(* Logix 5000 project; controller Test vendor 1 type 14 code 92 rev 33.11; software revision 33.03 *)

TASK MainTask (continuous, watchdog 500 ms) : MainProgram

MODULES
   Local : vendor 1 type 14 code 92 (ICP 0, rev 33.11)
      IN : vendor 1 type 7 code 1 (ICP 3, rev 3.2, Input RPI 20 ms)
      O : vendor 1 type 7 code 15 (ICP 2, rev 3.2, Output RPI 20 ms)
      Ethernet : 1756-ENBT (ICP 1, Ethernet 192.168.0.98, rev 6.4)
         IOLM1 : DXM (Ethernet 192.168.0.1, rev 2.22, StandardDataDriven RPI 20 ms)
END_MODULES

TYPE Banner_B25_Configuration_v4 :
STRUCT
   Sensor_Lockout : SINT;   // 0=Unlocked, 1=Locked
   Sensitivity : SINT;   // 0=Low, 1=Standard, 2=High
   Pin2_Function : SINT;   // 0=Disabled, 1=Remote Teach, 2=Detection Output, 3=Complementary Output, 4=NC Health, 5=NO Health
   Pin2_Pin4_Polarity : SINT;   // 0=NPN, 1=PNP, 2=Push Pull
   Output_Logic : SINT;   // 0=LO, 1= DO
   Output_Delay_Mode : SINT;   // 0=No Delay, 1=On/Off Delay
   Output_On_Delay : DINT;
   Output_Off_Delay : DINT;
   Dynamic_Teach_Timeout_Mode : SINT;   // 0=Cancel Teach, 1=Stop Teach
   Dynamic_Teach_Timeout_Duration : DINT;
   Alarm_Threshold : SINT;   // Set to 0% to disable alarm. Thresholds close to 100% will alarm near taught condition, thrsholds near 0% will alarm near sensor limits
   Display_Disable : SINT;   // 0=Enabled, 1=Disabled
   Drift_Filter_Enable : SINT;   // 0=Disabled, 1=Enabled
   Signal_Mode : SINT;   // Signal Mode - Signal places 100% at taught condition and 0% at no signal. Switchpoint Centric paces 100% at taught conditition and 50% at switchpoint.
END_STRUCT
END_TYPE

TYPE Banner_B25_PDI_v4 :   // Process Data for a B25. This will include event information.
STRUCT
   Output_State : SINT;   // 0 = Inactive, 1 = Active
   Alarm_State : SINT;   // 0 = Inactive, 1 = Active
   Signal_Level : SINT;   // Signal Mode - Signal places 100% at taught condition and 0% at no signal. Switchpoint Centric paces 100% at taught conditition and 50% at switchpoint.
END_STRUCT
END_TYPE

TYPE Banner_B25_RD_v4 :   // UDT that stores the Read Data for a B25.
STRUCT
   Direct : Banner_Direct_Parameters_v4;
   Serial_Number : STRING;
   Teach_State : SINT;   // 0=Idle, 1=SP1 Success, 2=SP2 Succes, 3=SP1 SP2 Success, 4 = Wait for Command, 5 = Busy, 7 = Error.
   Status : Banner_B25_Status_v4;
   All_Time_Run_Time_Counter : DINT;   // 0 to 2 Billion. 1/4 hr increments.
END_STRUCT
END_TYPE

TYPE Banner_B25_Status_v4 :
STRUCT
   Output_State : SINT;   // 0=Inactive, 1=Active
   Signal_Level : SINT;   // Signal Level - Switchpoit is at 50%, Taught Signal is at 100%
   Temperature : DINT;   // Internal Temperature
   Last_Taught_Temperature : DINT;   // Internal Temperature the last time device was taught
   Quality_of_Teach : SINT;   // 0=Not Taught, 1=Good, 2=Bad
   Health_Alarm_State : SINT;   // 0=No Alarm, 1= Alarm
   Quality_of_Health : INT;
END_STRUCT
END_TYPE

TYPE Banner_B25_v4 :   // All of the parameters for a B25.
STRUCT
   Initial_Global_Read : BOOL;   // Determines if all of the IO-Link data has been read into the PLC yet
   Command : INT;   // Value placed in here will activate a read or write to a specifc IO-Link Index
   Read : Banner_B25_RD_v4;   // Read Only Data
   Write : Banner_B25_WD_v4;   // Write Data
   Reset : BOOL;   // Resets AOI. This will force a complete parameter read of the sensor.
END_STRUCT
END_TYPE

TYPE Banner_B25_WD_v4 :   // UDT that stores the Write Data for a B25.
STRUCT
   System_Command : INT;   // See IODD file for list of commands that can be activated via the System Command interface
   Parameter_Access_Lock : SINT;   // Write access to all parameters is prohibited while value is 1. Only this parameter can be adjusted when value is 1.
   Data_Storage_Lock : SINT;   // Automatic data storage is disabled when this value is equal to 1. Read access is not affected.
   Local_Parameterization_Lock : SINT;   // Parameterization via local control elements on device is disabled.
   Local_User_Interface_Lock : SINT;   // Operation of local user interface is disabled.
   Configuration : Banner_B25_Configuration_v4;
   Resettable_Run_Time_Counter : DINT;   // 0 to 2 Billion. 1/4 hr increments.
   All_Time_Run_Time_Event_Time : DINT;   // 0 to 2 Billion. 1/4 hr increments.
   Resettable_Run_Time_Event_Time_Counter : DINT;   // 0 to 2 Billion. 1/4 hr increments.
END_STRUCT
END_TYPE

TYPE Banner_Direct_Parameters_v4 :
STRUCT
   Master_Cycle_Time : INT;
   Min_Cycle_Time : INT;
   M_Sequence_Capability : INT;
   IO_Link_Version_ID : INT;
   Process_Data_Input_Length : INT;
   Process_Data_Output_Length : INT;
   Combined_Vendor_ID : DINT;   // IO-Link Vendor ID
   Vendor_ID1 : INT;
   Vendor_ID2 : INT;
   Combined_Device_ID : DINT;   // IO-Link Device ID
   Device_ID1 : INT;
   Device_ID2 : INT;
   Device_ID3 : INT;
END_STRUCT
END_TYPE

TYPE Banner_IOL_Port_v4 :   // UDT that has all of the data items necessary to communicate with a specific Port on a IO-Link Master
STRUCT
   Port_Controlled : INT;   // Each bit represents a port on an IO-Link Master. Set to 1 to tell AOI to control that port.
   Port_Activate : INT;   // Each bit represents a port on an IO-Link Master. When ON that port will process any commands in queue.
   Port_Read : INT;   // Each bit represents a port on an IO-Link Master. Used to determine when device AOI has requested a Read command.
   Port_Write : INT;   // Each bit represents a port on an IO-Link Master. Used to determine when device AOI has requested a Write command.
   Port_RW_Complete : INT;   // Each bit represents a port on an IO-Link Master. Tells device AOI that Read or Write request has been completed.
   Port_Device_Read : INT;
   Data_Transfer : SINT[190];   // Array to transfer data from IO-Master to device AOIs.
END_STRUCT
END_TYPE

TYPE Banner_IOLM_EL_v4 :   // Error Log for Messages to IOLM.
STRUCT
   RW : SINT;   // 0 = Read, 1 = Write.
   Port : SINT;   // Port number that generated error.
   Index : INT;   // IO-Link Index for generated error.
END_STRUCT
END_TYPE

TYPE Banner_IOLM_v4 :   // UDT to control IO-Link Masters.
STRUCT
   Message_Source_Data : SINT[190];
   Message_Destination_Data : SINT[190];
   Error_Log : Banner_IOLM_EL_v4[10];
   Error_Write_Retry : BOOL;
   Num_Error_MSGS : DINT;
   IO_Link_Master_Busy : BOOL;   // 0 = While waiting for a command, 1 = Processing command
   AOI_Reset : BOOL;
   Port_Data : Banner_IOL_Port_v4;   // All of the necessary data to work with the various ports of the IO-Link Master.
   Halt_Operation : BOOL;   // When parameter is 1 the AOI is halted as next available time frame.
   AOI_Halted : BOOL;   // AOI is in standby mode until Halt Operation tag is set back to 0.
END_STRUCT
END_TYPE

ADD_ON_INSTRUCTION Banner_B25_Param_v4   (* revision 4.0, vendor Banner Engineering *)
// AOI to read and write parameter data to an IO-Link B25.
VAR_IN_OUT
   B25 : Banner_B25_v4; {required}
   Port_Data : Banner_IOL_Port_v4; {required}
END_VAR
VAR_INPUT
   Port : DINT; {required}
END_VAR
VAR
   Local_Control : DINT; {access None}
   Global_Read_Command_Value : INT; {access None}
   Global_Write_Command_Value : INT; {access None}
   Command_Being_Processed : BOOL; {access None}
   Update_Archive : BOOL; {access None}
   Index_Write_Inprocess : INT; {access None}
   Index_Write_Control : INT; {access None}
   Inprocess_Index : DINT; {access None}
END_VAR

ROUTINE Logic   (* ladder *)
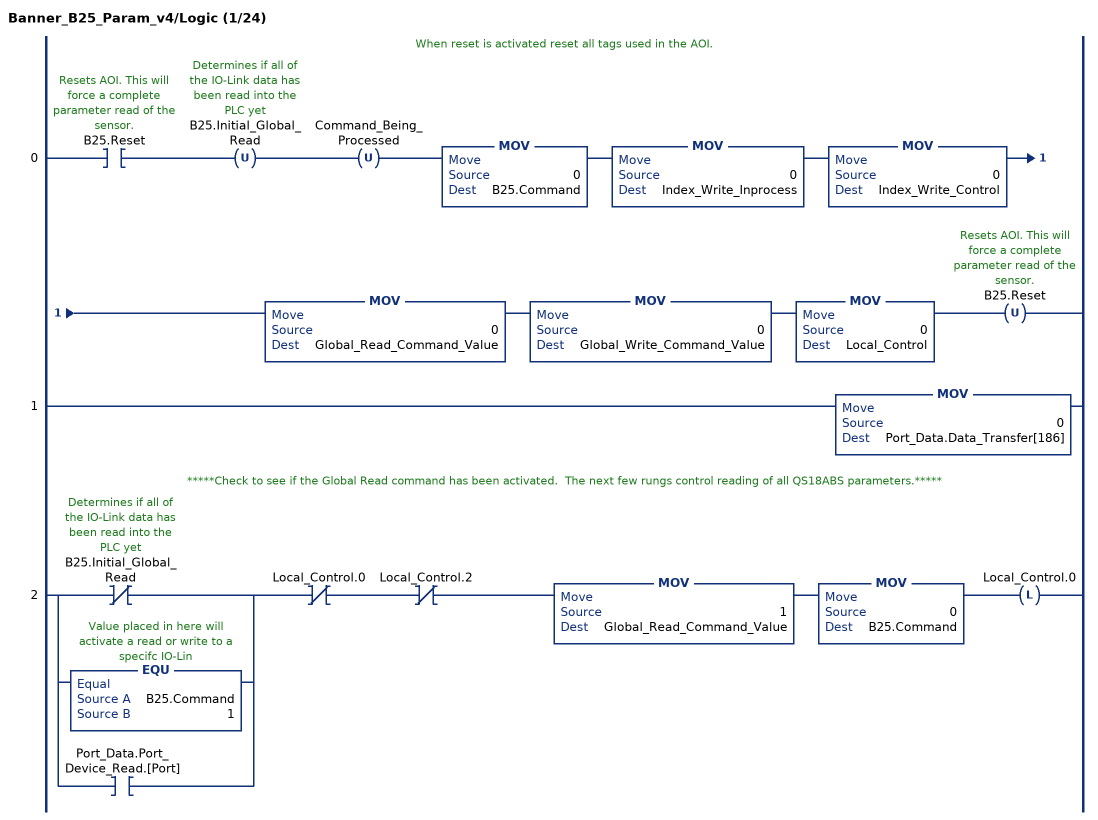
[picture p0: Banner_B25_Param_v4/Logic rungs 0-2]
   // When reset is activated reset all tags used in the AOI.
   0: XIC(B25.Reset)OTU(B25.Initial_Global_Read)OTU(Command_Being_Processed)MOV(0,B25.Command)MOV(0,Index_Write_Inprocess)MOV(0,Index_Write_Control)MOV(0,Global_Read_Command_Value)MOV(0,Global_Write_Command_Value)MOV(0,Local_Control)OTU(B25.Reset);
   1: MOV(0,Port_Data.Data_Transfer[186]);
   // *****Check to see if the Global Read command has been activated.  The next few rungs control reading of all QS18ABS parameters.*****
   2: [XIO(B25.Initial_Global_Read) ,EQU(B25.Command,1) ,XIC(Port_Data.Port_Device_Read.[Port]) ]XIO(Local_Control.0)XIO(Local_Control.2)MOV(1,Global_Read_Command_Value)MOV(0,B25.Command)OTL(Local_Control.0);
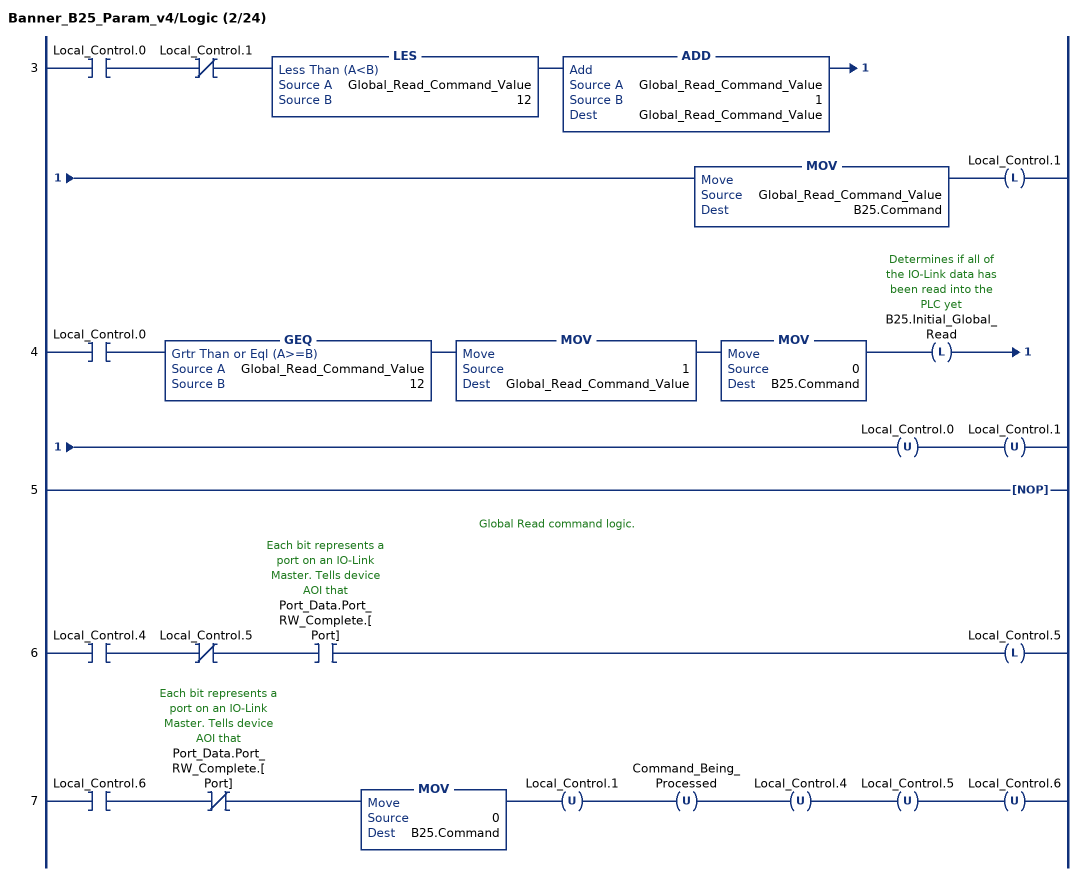
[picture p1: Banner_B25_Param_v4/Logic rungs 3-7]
   3: XIC(Local_Control.0)XIO(Local_Control.1)LES(Global_Read_Command_Value,12)ADD(Global_Read_Command_Value,1,Global_Read_Command_Value)MOV(Global_Read_Command_Value,B25.Command)OTL(Local_Control.1);
   4: XIC(Local_Control.0)GEQ(Global_Read_Command_Value,12)MOV(1,Global_Read_Command_Value)MOV(0,B25.Command)OTL(B25.Initial_Global_Read)OTU(Local_Control.0)OTU(Local_Control.1);
   5: NOP();
   // Global Read command logic.
   6: XIC(Local_Control.4)XIO(Local_Control.5)XIC(Port_Data.Port_RW_Complete.[Port])OTL(Local_Control.5);
   7: XIC(Local_Control.6)XIO(Port_Data.Port_RW_Complete.[Port])MOV(0,B25.Command)OTU(Local_Control.1)OTU(Command_Being_Processed)OTU(Local_Control.4)OTU(Local_Control.5)OTU(Local_Control.6);
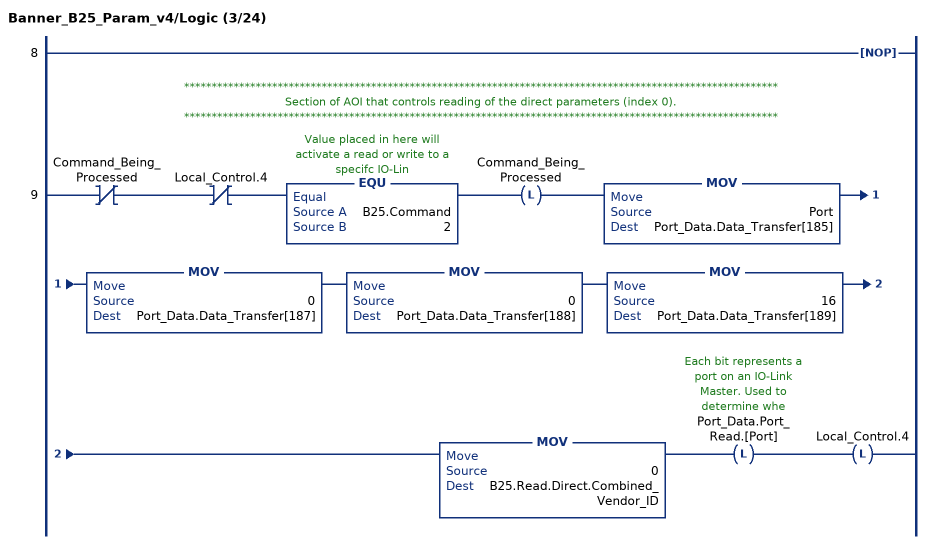
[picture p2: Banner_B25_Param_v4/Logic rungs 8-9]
   8: NOP();
   // ************************************************************************************************************
   // Section of AOI that controls reading of the direct parameters (index 0).
   // ************************************************************************************************************
   9: XIO(Command_Being_Processed)XIO(Local_Control.4)EQU(B25.Command,2)OTL(Command_Being_Processed)MOV(Port,Port_Data.Data_Transfer[185])MOV(0,Port_Data.Data_Transfer[187])MOV(0,Port_Data.Data_Transfer[188])MOV(16,Port_Data.Data_Transfer[189])MOV(0,B25.Read.Direct.Combined_Vendor_ID)OTL(Port_Data.Port_Read.[Port])OTL(Local_Control.4);
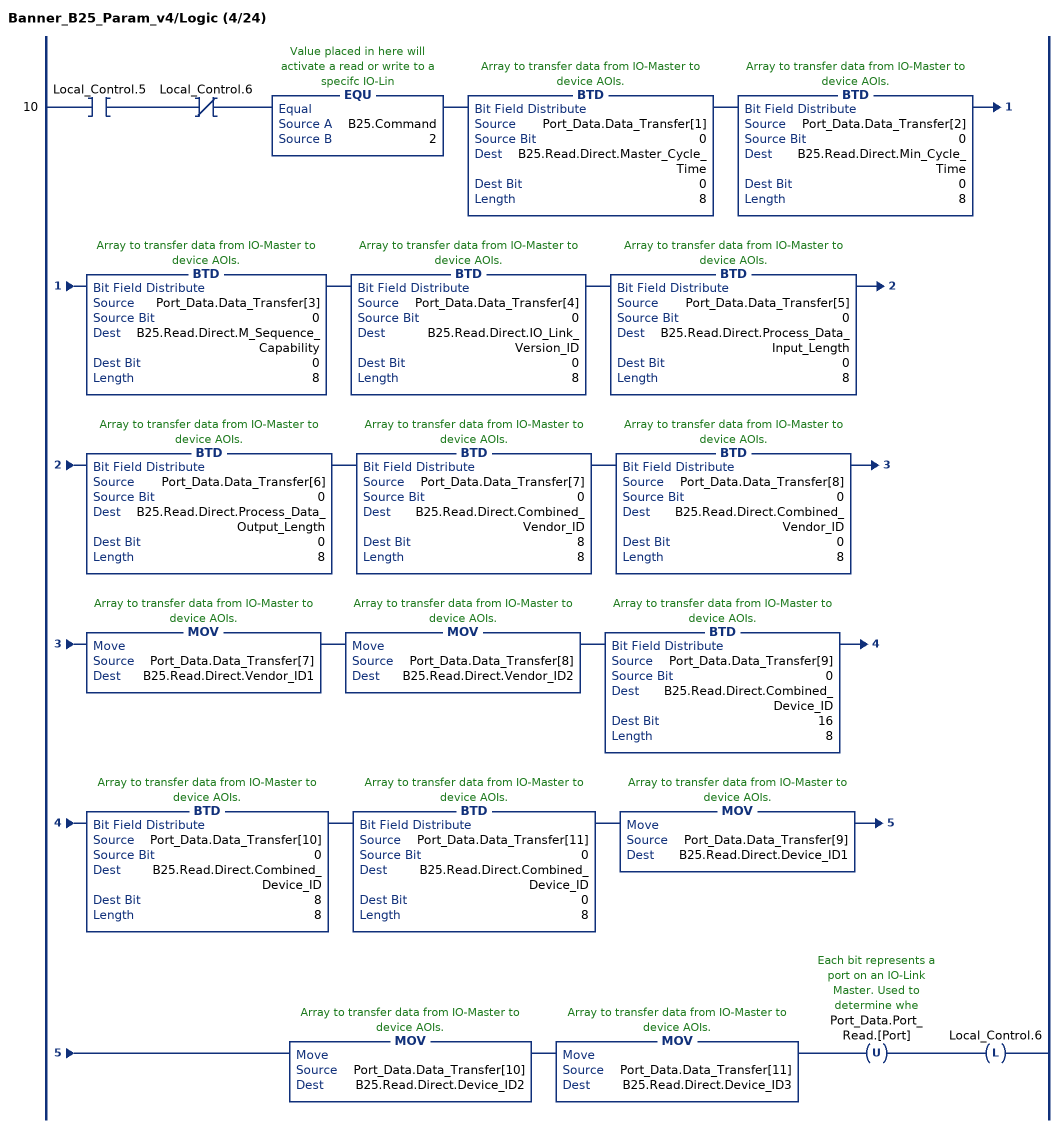
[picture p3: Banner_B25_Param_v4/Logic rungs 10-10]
   10: XIC(Local_Control.5)XIO(Local_Control.6)EQU(B25.Command,2)BTD(Port_Data.Data_Transfer[1],0,B25.Read.Direct.Master_Cycle_Time,0,8)BTD(Port_Data.Data_Transfer[2],0,B25.Read.Direct.Min_Cycle_Time,0,8)BTD(Port_Data.Data_Transfer[3],0,B25.Read.Direct.M_Sequence_Capability,0,8)BTD(Port_Data.Data_Transfer[4],0,B25.Read.Direct.IO_Link_Version_ID,0,8)BTD(Port_Data.Data_Transfer[5],0,B25.Read.Direct.Process_Data_Input_Length,0,8)BTD(Port_Data.Data_Transfer[6],0,B25.Read.Direct.Process_Data_Output_Length,0,8)BTD(Port_Data.Data_Transfer[7],0,B25.Read.Direct.Combined_Vendor_ID,8,8)BTD(Port_Data.Data_Transfer[8],0,B25.Read.Direct.Combined_Vendor_ID,0,8)MOV(Port_Data.Data_Transfer[7],B25.Read.Direct.Vendor_ID1)MOV(Port_Data.Data_Transfer[8],B25.Read.Direct.Vendor_ID2)BTD(Port_Data.Data_Transfer[9],0,B25.Read.Direct.Combined_Device_ID,16,8)BTD(Port_Data.Data_Transfer[10],0,B25.Read.Direct.Combined_Device_ID,8,8)BTD(Port_Data.Data_Transfer[11],0,B25.Read.Direct.Combined_Device_ID,0,8)MOV(Port_Data.Data_Transfer[9],B25.Read.Direct.Device_ID1)MOV(Port_Data.Data_Transfer[10],B25.Read.Direct.Device_ID2)MOV(Port_Data.Data_Transfer[11],B25.Read.Direct.Device_ID3)OTU(Port_Data.Port_Read.[Port])OTL(Local_Control.6);
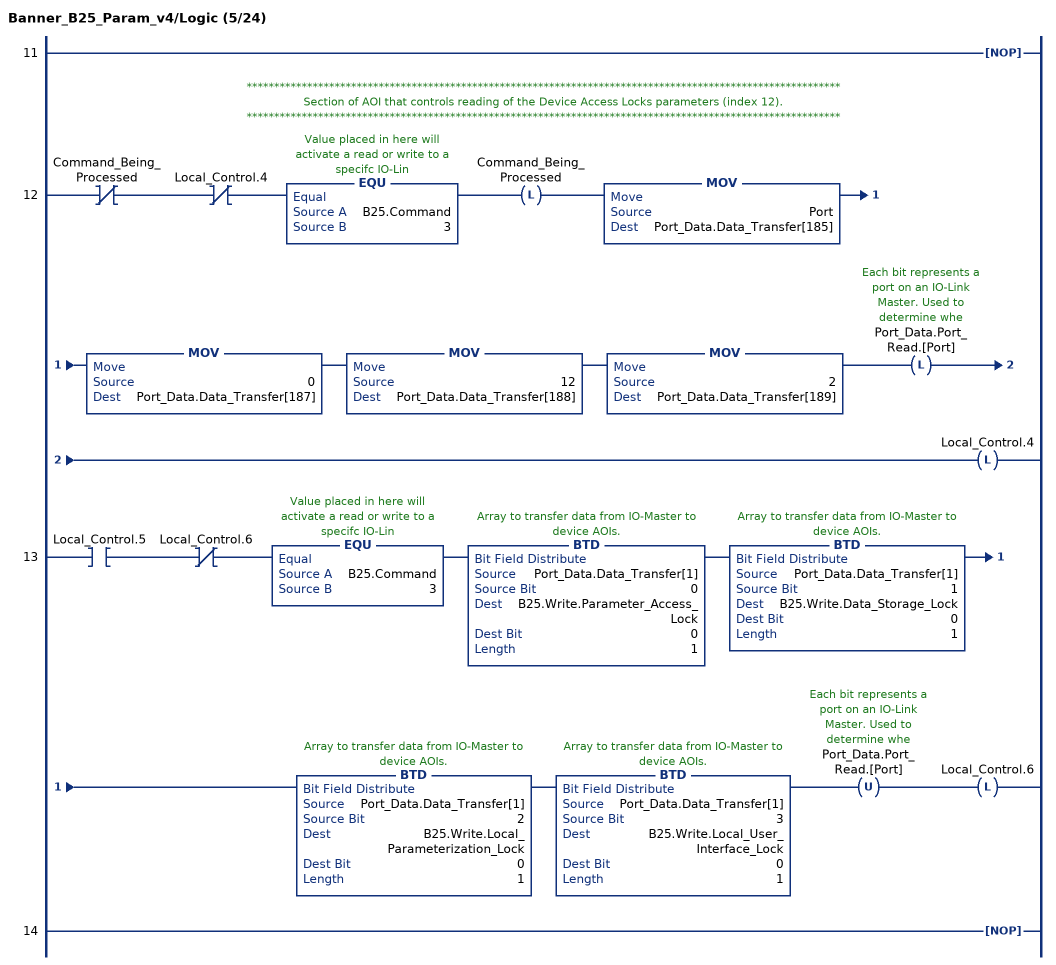
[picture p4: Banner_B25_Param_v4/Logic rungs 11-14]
   11: NOP();
   // ************************************************************************************************************
   // Section of AOI that controls reading of the Device Access Locks parameters (index 12).
   // ************************************************************************************************************
   12: XIO(Command_Being_Processed)XIO(Local_Control.4)EQU(B25.Command,3)OTL(Command_Being_Processed)MOV(Port,Port_Data.Data_Transfer[185])MOV(0,Port_Data.Data_Transfer[187])MOV(12,Port_Data.Data_Transfer[188])MOV(2,Port_Data.Data_Transfer[189])OTL(Port_Data.Port_Read.[Port])OTL(Local_Control.4);
   13: XIC(Local_Control.5)XIO(Local_Control.6)EQU(B25.Command,3)BTD(Port_Data.Data_Transfer[1],0,B25.Write.Parameter_Access_Lock,0,1)BTD(Port_Data.Data_Transfer[1],1,B25.Write.Data_Storage_Lock,0,1)BTD(Port_Data.Data_Transfer[1],2,B25.Write.Local_Parameterization_Lock,0,1)BTD(Port_Data.Data_Transfer[1],3,B25.Write.Local_User_Interface_Lock,0,1)OTU(Port_Data.Port_Read.[Port])OTL(Local_Control.6);
   14: NOP();
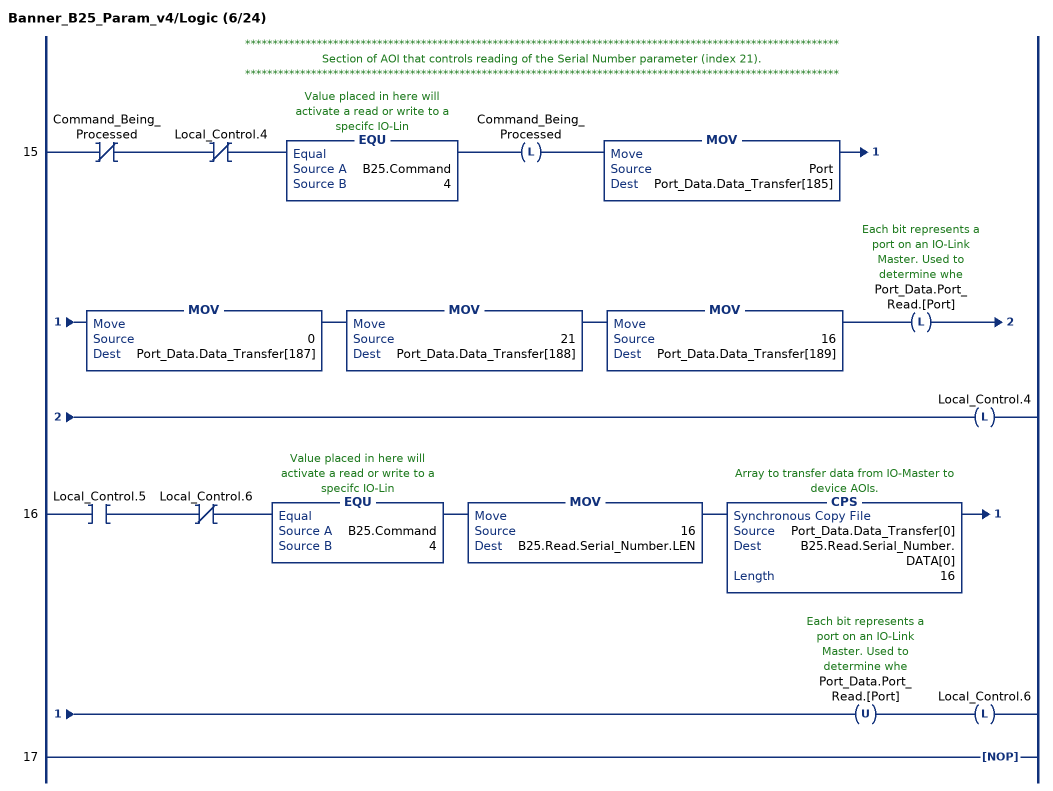
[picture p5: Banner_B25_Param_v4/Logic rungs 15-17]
   // ************************************************************************************************************
   // Section of AOI that controls reading of the Serial Number parameter (index 21).
   // ************************************************************************************************************
   15: XIO(Command_Being_Processed)XIO(Local_Control.4)EQU(B25.Command,4)OTL(Command_Being_Processed)MOV(Port,Port_Data.Data_Transfer[185])MOV(0,Port_Data.Data_Transfer[187])MOV(21,Port_Data.Data_Transfer[188])MOV(16,Port_Data.Data_Transfer[189])OTL(Port_Data.Port_Read.[Port])OTL(Local_Control.4);
   16: XIC(Local_Control.5)XIO(Local_Control.6)EQU(B25.Command,4)MOV(16,B25.Read.Serial_Number.LEN)CPS(Port_Data.Data_Transfer[0],B25.Read.Serial_Number.DATA[0],16)OTU(Port_Data.Port_Read.[Port])OTL(Local_Control.6);
   17: NOP();
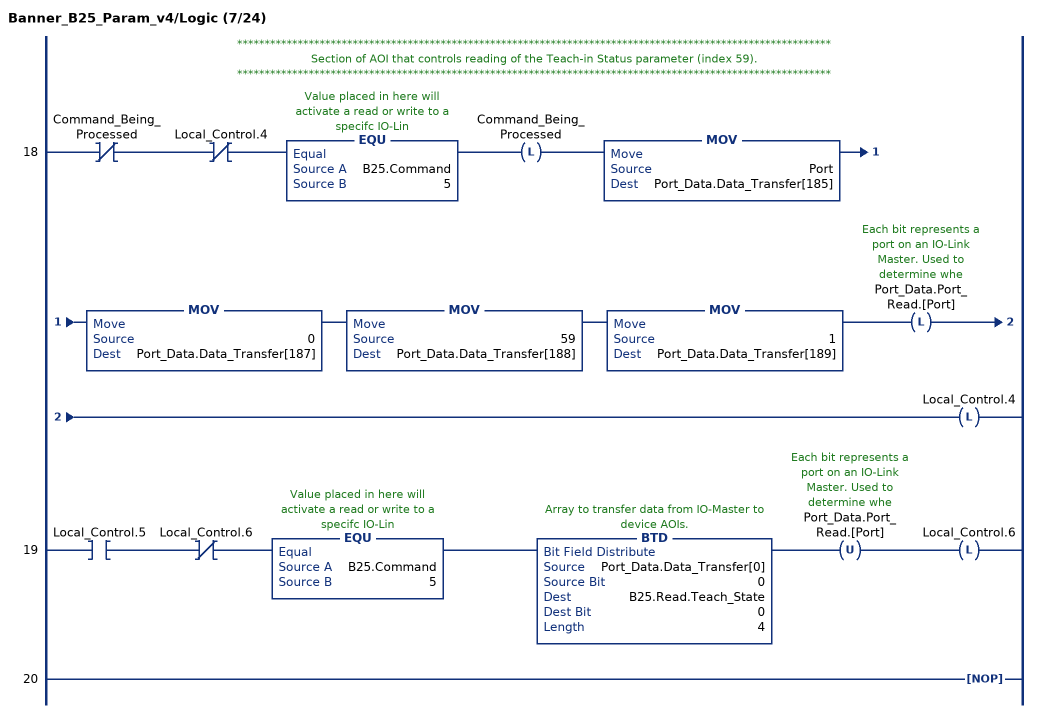
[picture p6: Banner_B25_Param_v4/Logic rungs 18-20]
   // ************************************************************************************************************
   // Section of AOI that controls reading of the Teach-in Status parameter (index 59).
   // ************************************************************************************************************
   18: XIO(Command_Being_Processed)XIO(Local_Control.4)EQU(B25.Command,5)OTL(Command_Being_Processed)MOV(Port,Port_Data.Data_Transfer[185])MOV(0,Port_Data.Data_Transfer[187])MOV(59,Port_Data.Data_Transfer[188])MOV(1,Port_Data.Data_Transfer[189])OTL(Port_Data.Port_Read.[Port])OTL(Local_Control.4);
   19: XIC(Local_Control.5)XIO(Local_Control.6)EQU(B25.Command,5)BTD(Port_Data.Data_Transfer[0],0,B25.Read.Teach_State,0,4)OTU(Port_Data.Port_Read.[Port])OTL(Local_Control.6);
   20: NOP();
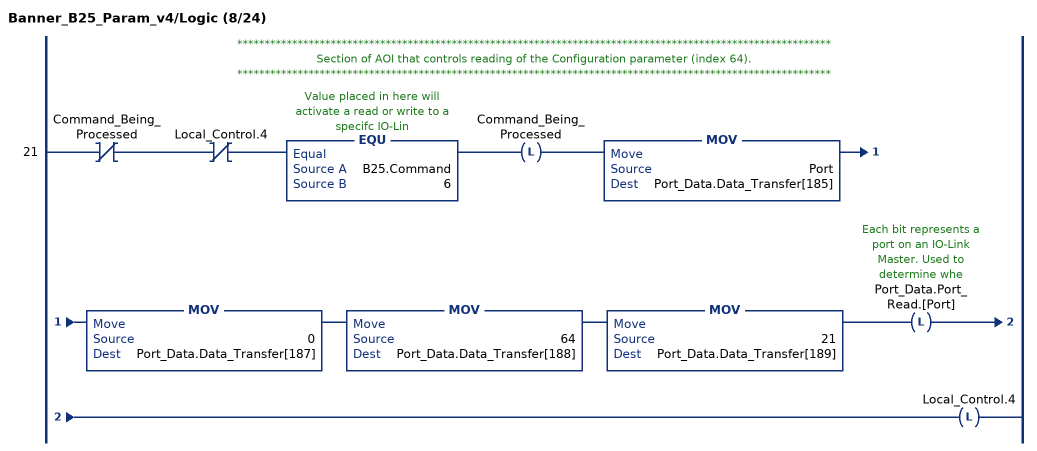
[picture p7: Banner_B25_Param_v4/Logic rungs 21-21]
   // ************************************************************************************************************
   // Section of AOI that controls reading of the Configuration parameter (index 64).
   // ************************************************************************************************************
   21: XIO(Command_Being_Processed)XIO(Local_Control.4)EQU(B25.Command,6)OTL(Command_Being_Processed)MOV(Port,Port_Data.Data_Transfer[185])MOV(0,Port_Data.Data_Transfer[187])MOV(64,Port_Data.Data_Transfer[188])MOV(21,Port_Data.Data_Transfer[189])OTL(Port_Data.Port_Read.[Port])OTL(Local_Control.4);
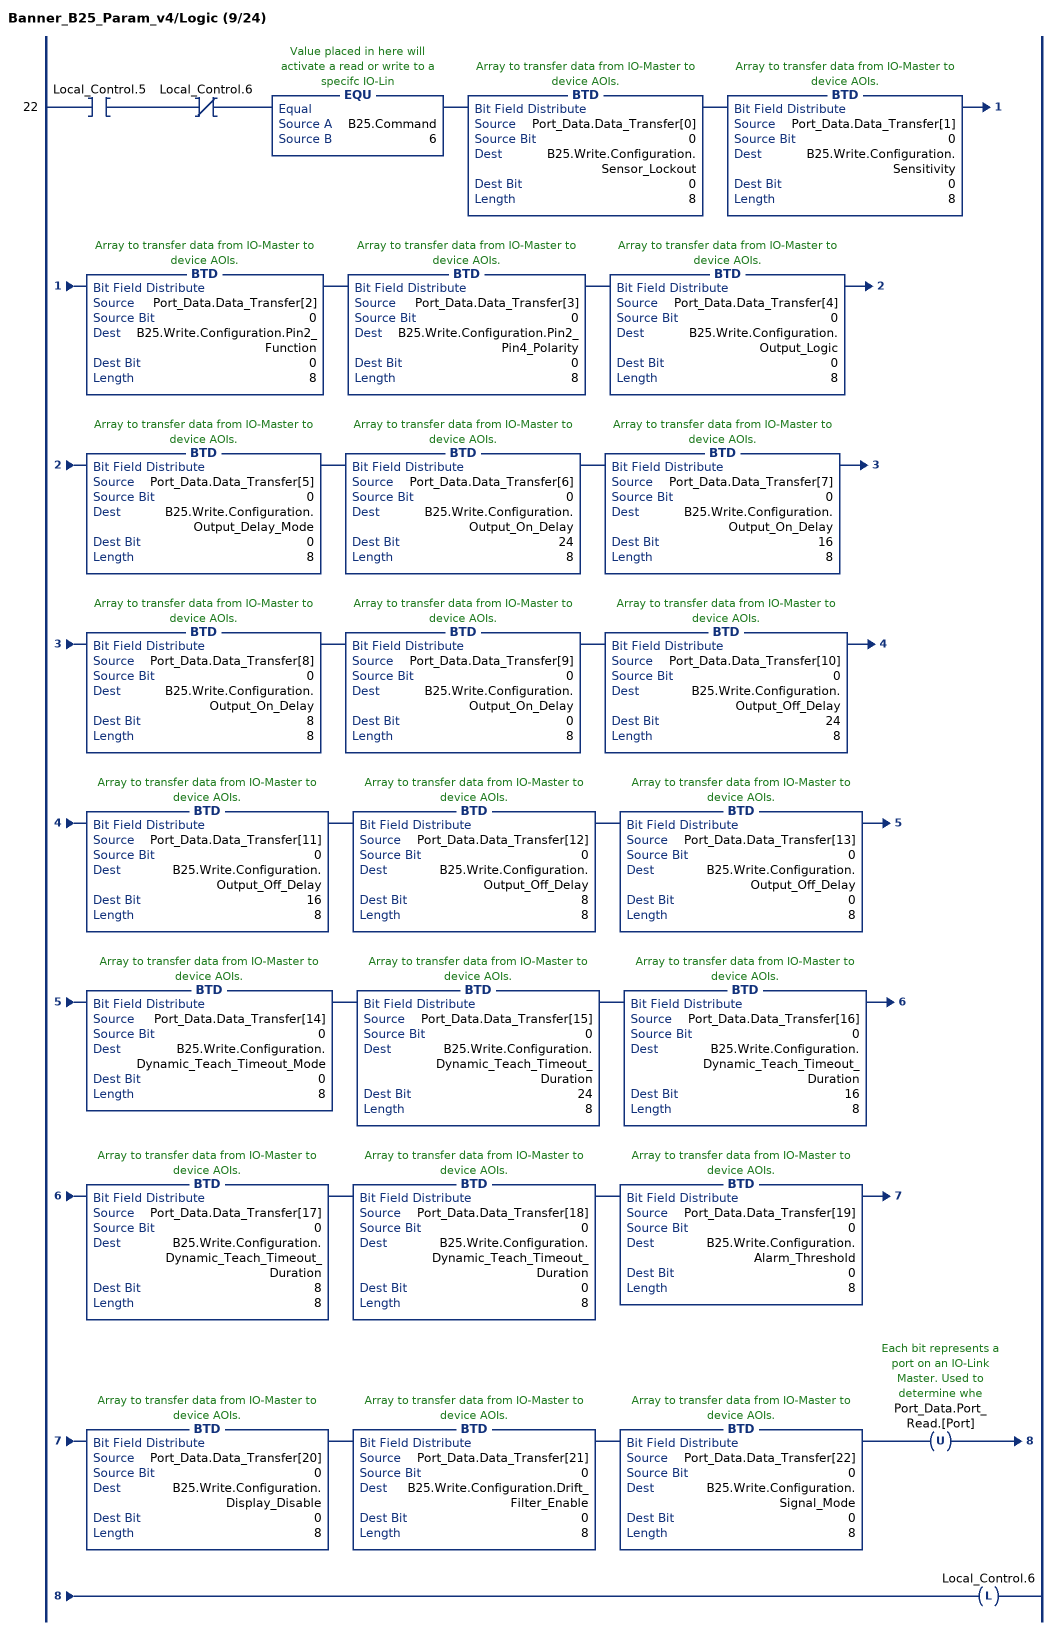
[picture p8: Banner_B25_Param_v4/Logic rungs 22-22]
   22: XIC(Local_Control.5)XIO(Local_Control.6)EQU(B25.Command,6)BTD(Port_Data.Data_Transfer[0],0,B25.Write.Configuration.Sensor_Lockout,0,8)BTD(Port_Data.Data_Transfer[1],0,B25.Write.Configuration.Sensitivity,0,8)BTD(Port_Data.Data_Transfer[2],0,B25.Write.Configuration.Pin2_Function,0,8)BTD(Port_Data.Data_Transfer[3],0,B25.Write.Configuration.Pin2_Pin4_Polarity,0,8)BTD(Port_Data.Data_Transfer[4],0,B25.Write.Configuration.Output_Logic,0,8)BTD(Port_Data.Data_Transfer[5],0,B25.Write.Configuration.Output_Delay_Mode,0,8)BTD(Port_Data.Data_Transfer[6],0,B25.Write.Configuration.Output_On_Delay,24,8)BTD(Port_Data.Data_Transfer[7],0,B25.Write.Configuration.Output_On_Delay,16,8)BTD(Port_Data.Data_Transfer[8],0,B25.Write.Configuration.Output_On_Delay,8,8)BTD(Port_Data.Data_Transfer[9],0,B25.Write.Configuration.Output_On_Delay,0,8)BTD(Port_Data.Data_Transfer[10],0,B25.Write.Configuration.Output_Off_Delay,24,8)BTD(Port_Data.Data_Transfer[11],0,B25.Write.Configuration.Output_Off_Delay,16,8)BTD(Port_Data.Data_Transfer[12],0,B25.Write.Configuration.Output_Off_Delay,8,8)BTD(Port_Data.Data_Transfer[13],0,B25.Write.Configuration.Output_Off_Delay,0,8)BTD(Port_Data.Data_Transfer[14],0,B25.Write.Configuration.Dynamic_Teach_Timeout_Mode,0,8)BTD(Port_Data.Data_Transfer[15],0,B25.Write.Configuration.Dynamic_Teach_Timeout_Duration,24,8)BTD(Port_Data.Data_Transfer[16],0,B25.Write.Configuration.Dynamic_Teach_Timeout_Duration,16,8)BTD(Port_Data.Data_Transfer[17],0,B25.Write.Configuration.Dynamic_Teach_Timeout_Duration,8,8)BTD(Port_Data.Data_Transfer[18],0,B25.Write.Configuration.Dynamic_Teach_Timeout_Duration,0,8)BTD(Port_Data.Data_Transfer[19],0,B25.Write.Configuration.Alarm_Threshold,0,8)BTD(Port_Data.Data_Transfer[20],0,B25.Write.Configuration.Display_Disable,0,8)BTD(Port_Data.Data_Transfer[21],0,B25.Write.Configuration.Drift_Filter_Enable,0,8)BTD(Port_Data.Data_Transfer[22],0,B25.Write.Configuration.Signal_Mode,0,8)OTU(Port_Data.Port_Read.[Port])OTL(Local_Control.6);
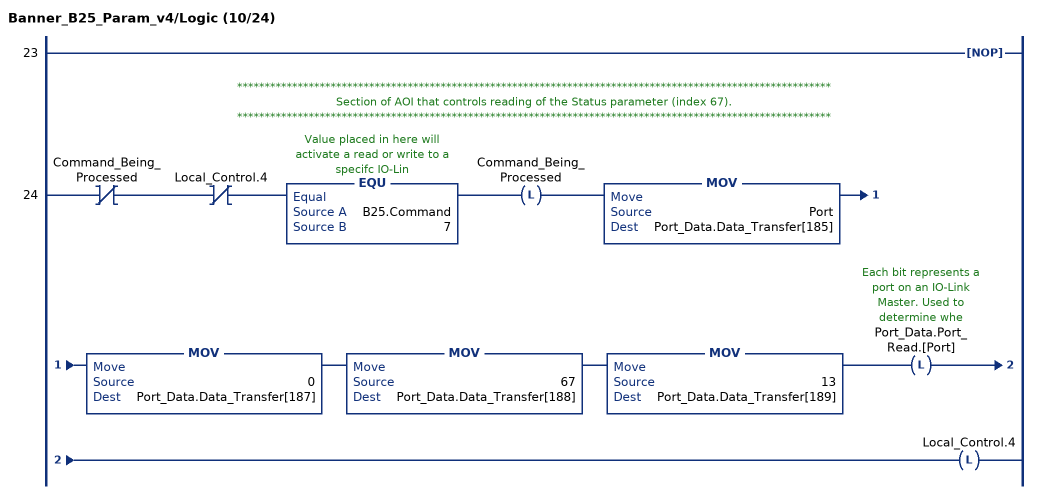
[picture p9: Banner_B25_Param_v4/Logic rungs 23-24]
   23: NOP();
   // ************************************************************************************************************
   // Section of AOI that controls reading of the Status parameter (index 67).
   // ************************************************************************************************************
   24: XIO(Command_Being_Processed)XIO(Local_Control.4)EQU(B25.Command,7)OTL(Command_Being_Processed)MOV(Port,Port_Data.Data_Transfer[185])MOV(0,Port_Data.Data_Transfer[187])MOV(67,Port_Data.Data_Transfer[188])MOV(13,Port_Data.Data_Transfer[189])OTL(Port_Data.Port_Read.[Port])OTL(Local_Control.4);
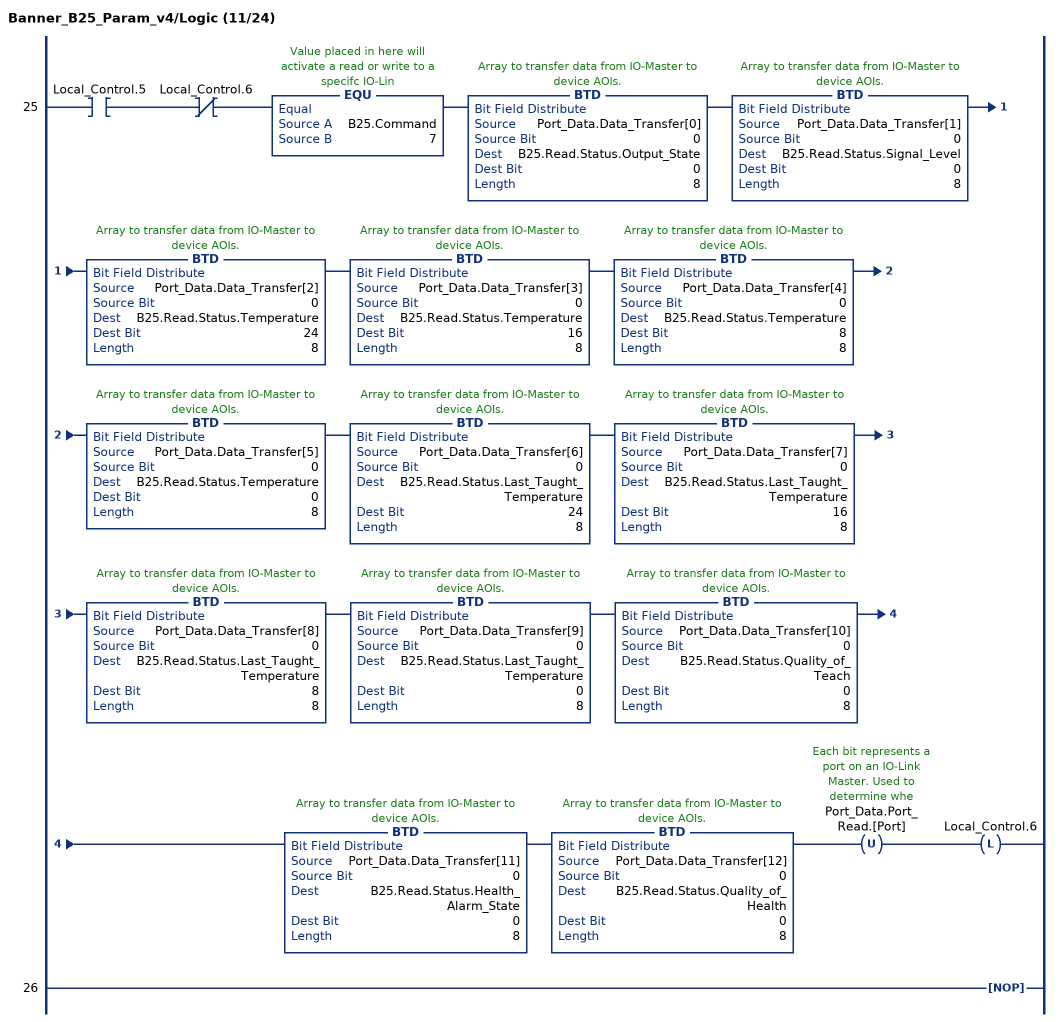
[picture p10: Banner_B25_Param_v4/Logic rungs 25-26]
   25: XIC(Local_Control.5)XIO(Local_Control.6)EQU(B25.Command,7)BTD(Port_Data.Data_Transfer[0],0,B25.Read.Status.Output_State,0,8)BTD(Port_Data.Data_Transfer[1],0,B25.Read.Status.Signal_Level,0,8)BTD(Port_Data.Data_Transfer[2],0,B25.Read.Status.Temperature,24,8)BTD(Port_Data.Data_Transfer[3],0,B25.Read.Status.Temperature,16,8)BTD(Port_Data.Data_Transfer[4],0,B25.Read.Status.Temperature,8,8)BTD(Port_Data.Data_Transfer[5],0,B25.Read.Status.Temperature,0,8)BTD(Port_Data.Data_Transfer[6],0,B25.Read.Status.Last_Taught_Temperature,24,8)BTD(Port_Data.Data_Transfer[7],0,B25.Read.Status.Last_Taught_Temperature,16,8)BTD(Port_Data.Data_Transfer[8],0,B25.Read.Status.Last_Taught_Temperature,8,8)BTD(Port_Data.Data_Transfer[9],0,B25.Read.Status.Last_Taught_Temperature,0,8)BTD(Port_Data.Data_Transfer[10],0,B25.Read.Status.Quality_of_Teach,0,8)BTD(Port_Data.Data_Transfer[11],0,B25.Read.Status.Health_Alarm_State,0,8)BTD(Port_Data.Data_Transfer[12],0,B25.Read.Status.Quality_of_Health,0,8)OTU(Port_Data.Port_Read.[Port])OTL(Local_Control.6);
   26: NOP();
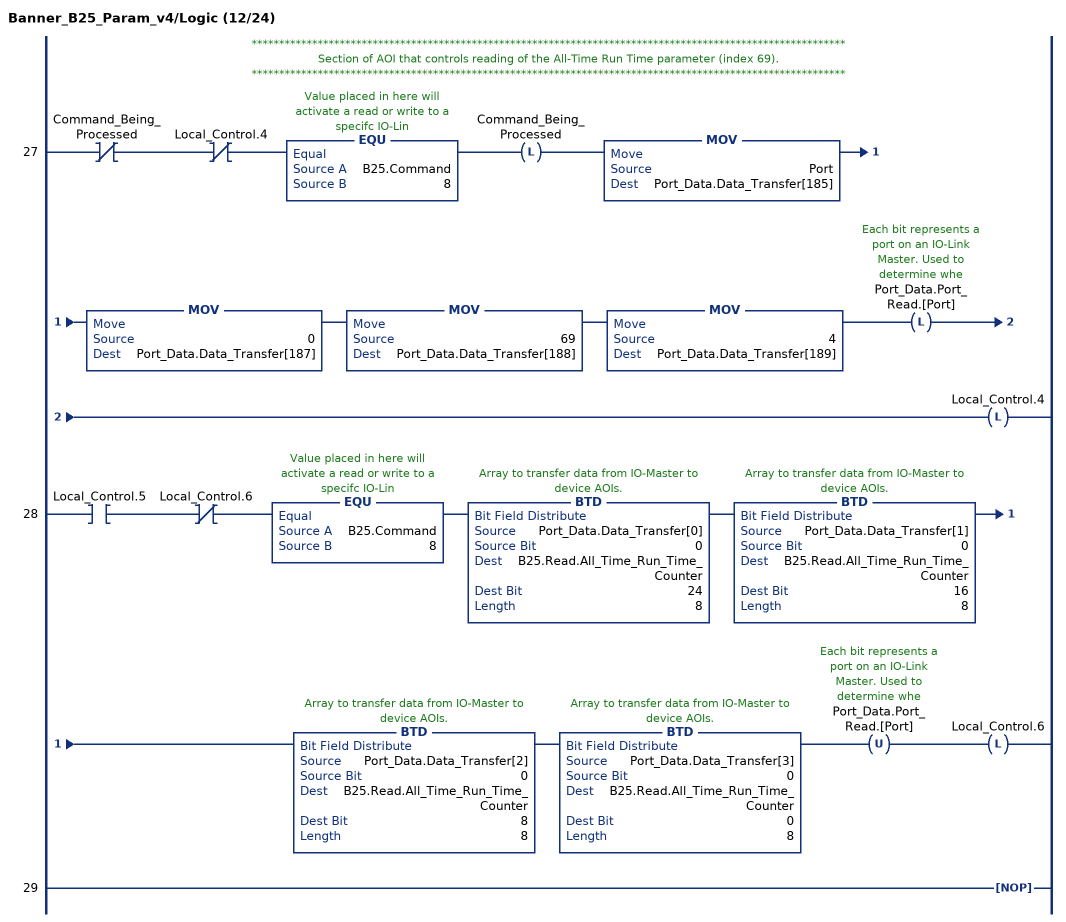
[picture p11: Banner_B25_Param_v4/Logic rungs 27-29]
   // ************************************************************************************************************
   // Section of AOI that controls reading of the All-Time Run Time parameter (index 69).
   // ************************************************************************************************************
   27: XIO(Command_Being_Processed)XIO(Local_Control.4)EQU(B25.Command,8)OTL(Command_Being_Processed)MOV(Port,Port_Data.Data_Transfer[185])MOV(0,Port_Data.Data_Transfer[187])MOV(69,Port_Data.Data_Transfer[188])MOV(4,Port_Data.Data_Transfer[189])OTL(Port_Data.Port_Read.[Port])OTL(Local_Control.4);
   28: XIC(Local_Control.5)XIO(Local_Control.6)EQU(B25.Command,8)BTD(Port_Data.Data_Transfer[0],0,B25.Read.All_Time_Run_Time_Counter,24,8)BTD(Port_Data.Data_Transfer[1],0,B25.Read.All_Time_Run_Time_Counter,16,8)BTD(Port_Data.Data_Transfer[2],0,B25.Read.All_Time_Run_Time_Counter,8,8)BTD(Port_Data.Data_Transfer[3],0,B25.Read.All_Time_Run_Time_Counter,0,8)OTU(Port_Data.Port_Read.[Port])OTL(Local_Control.6);
   29: NOP();
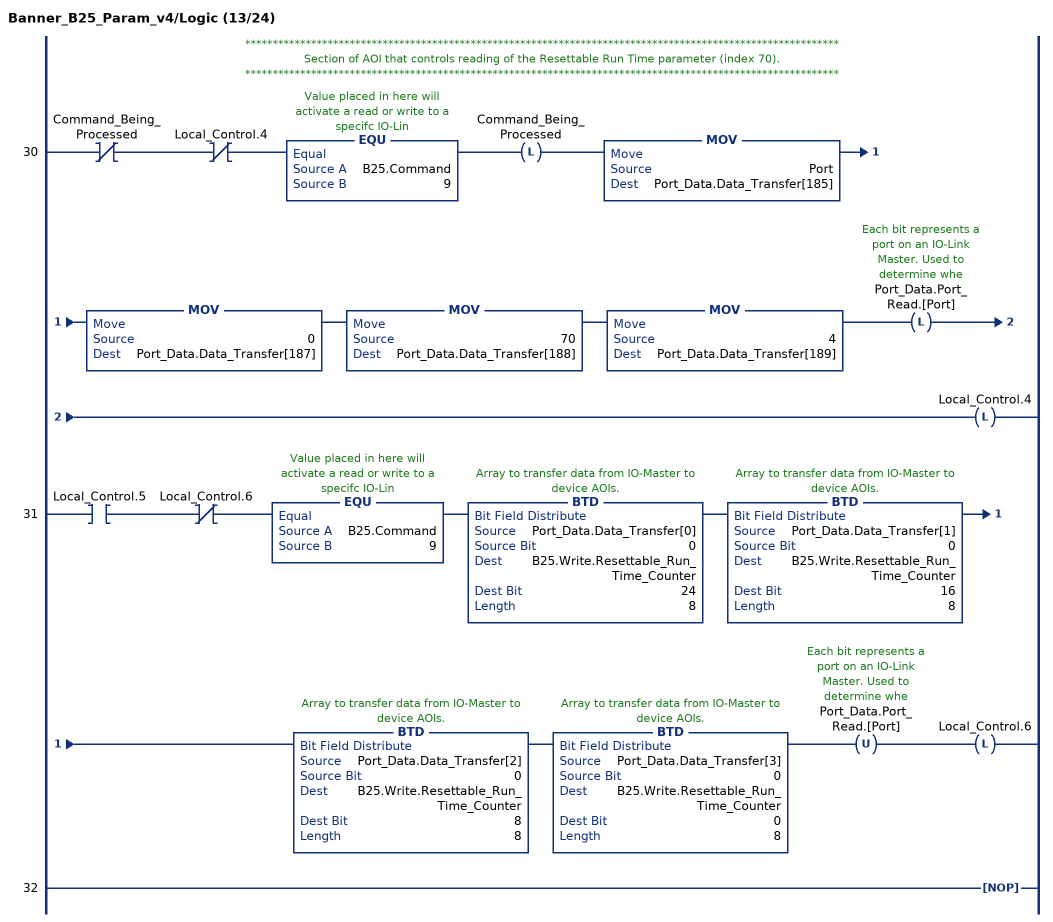
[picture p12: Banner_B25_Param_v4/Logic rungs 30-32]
   // ************************************************************************************************************
   // Section of AOI that controls reading of the Resettable Run Time parameter (index 70).
   // ************************************************************************************************************
   30: XIO(Command_Being_Processed)XIO(Local_Control.4)EQU(B25.Command,9)OTL(Command_Being_Processed)MOV(Port,Port_Data.Data_Transfer[185])MOV(0,Port_Data.Data_Transfer[187])MOV(70,Port_Data.Data_Transfer[188])MOV(4,Port_Data.Data_Transfer[189])OTL(Port_Data.Port_Read.[Port])OTL(Local_Control.4);
   31: XIC(Local_Control.5)XIO(Local_Control.6)EQU(B25.Command,9)BTD(Port_Data.Data_Transfer[0],0,B25.Write.Resettable_Run_Time_Counter,24,8)BTD(Port_Data.Data_Transfer[1],0,B25.Write.Resettable_Run_Time_Counter,16,8)BTD(Port_Data.Data_Transfer[2],0,B25.Write.Resettable_Run_Time_Counter,8,8)BTD(Port_Data.Data_Transfer[3],0,B25.Write.Resettable_Run_Time_Counter,0,8)OTU(Port_Data.Port_Read.[Port])OTL(Local_Control.6);
   32: NOP();
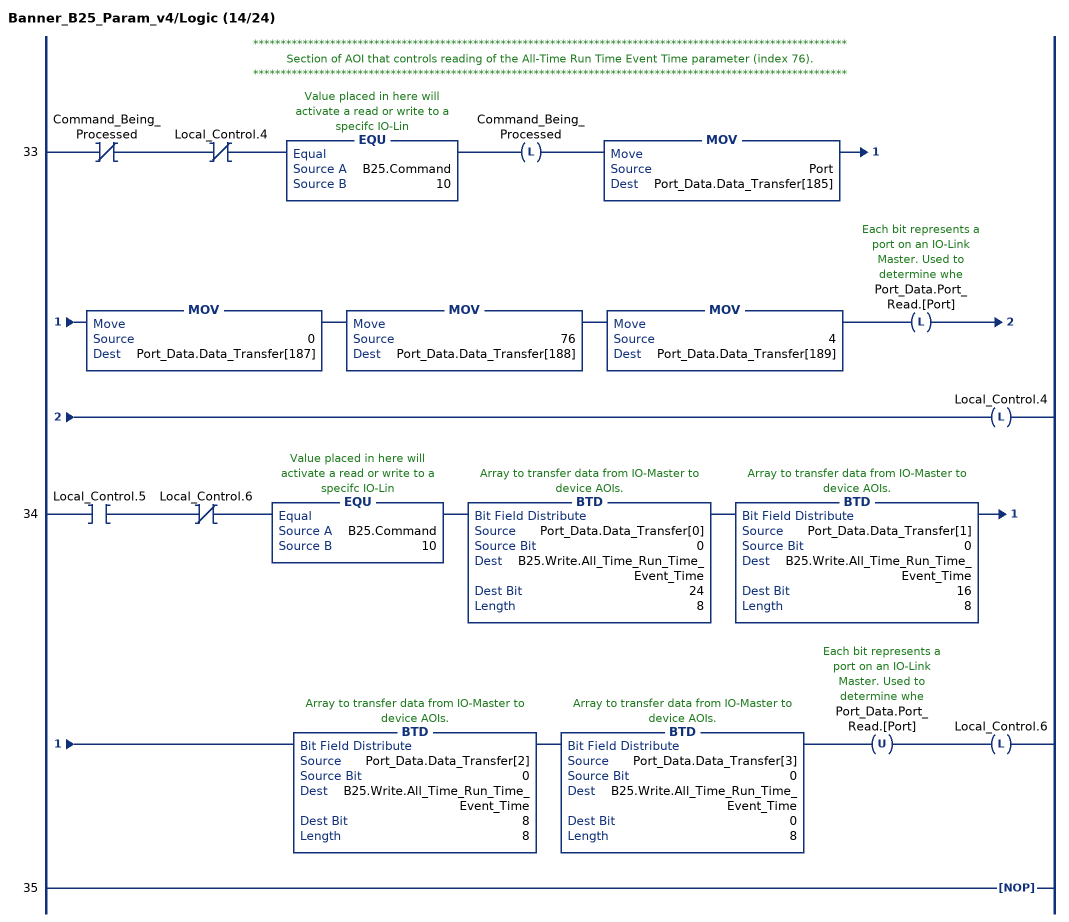
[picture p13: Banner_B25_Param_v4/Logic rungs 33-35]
   // ************************************************************************************************************
   // Section of AOI that controls reading of the All-Time Run Time Event Time parameter (index 76).
   // ************************************************************************************************************
   33: XIO(Command_Being_Processed)XIO(Local_Control.4)EQU(B25.Command,10)OTL(Command_Being_Processed)MOV(Port,Port_Data.Data_Transfer[185])MOV(0,Port_Data.Data_Transfer[187])MOV(76,Port_Data.Data_Transfer[188])MOV(4,Port_Data.Data_Transfer[189])OTL(Port_Data.Port_Read.[Port])OTL(Local_Control.4);
   34: XIC(Local_Control.5)XIO(Local_Control.6)EQU(B25.Command,10)BTD(Port_Data.Data_Transfer[0],0,B25.Write.All_Time_Run_Time_Event_Time,24,8)BTD(Port_Data.Data_Transfer[1],0,B25.Write.All_Time_Run_Time_Event_Time,16,8)BTD(Port_Data.Data_Transfer[2],0,B25.Write.All_Time_Run_Time_Event_Time,8,8)BTD(Port_Data.Data_Transfer[3],0,B25.Write.All_Time_Run_Time_Event_Time,0,8)OTU(Port_Data.Port_Read.[Port])OTL(Local_Control.6);
   35: NOP();
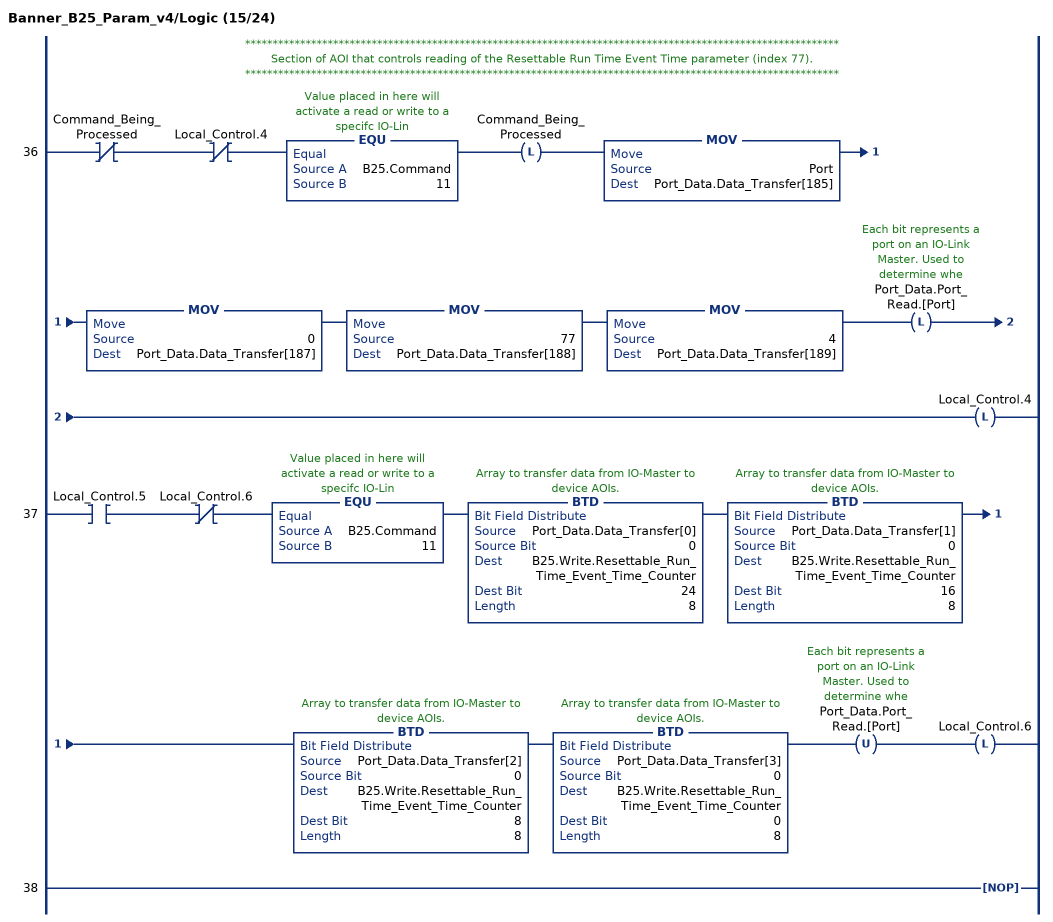
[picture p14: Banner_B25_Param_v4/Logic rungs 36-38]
   // ************************************************************************************************************
   // Section of AOI that controls reading of the Resettable Run Time Event Time parameter (index 77).
   // ************************************************************************************************************
   36: XIO(Command_Being_Processed)XIO(Local_Control.4)EQU(B25.Command,11)OTL(Command_Being_Processed)MOV(Port,Port_Data.Data_Transfer[185])MOV(0,Port_Data.Data_Transfer[187])MOV(77,Port_Data.Data_Transfer[188])MOV(4,Port_Data.Data_Transfer[189])OTL(Port_Data.Port_Read.[Port])OTL(Local_Control.4);
   37: XIC(Local_Control.5)XIO(Local_Control.6)EQU(B25.Command,11)BTD(Port_Data.Data_Transfer[0],0,B25.Write.Resettable_Run_Time_Event_Time_Counter,24,8)BTD(Port_Data.Data_Transfer[1],0,B25.Write.Resettable_Run_Time_Event_Time_Counter,16,8)BTD(Port_Data.Data_Transfer[2],0,B25.Write.Resettable_Run_Time_Event_Time_Counter,8,8)BTD(Port_Data.Data_Transfer[3],0,B25.Write.Resettable_Run_Time_Event_Time_Counter,0,8)OTU(Port_Data.Port_Read.[Port])OTL(Local_Control.6);
   38: NOP();
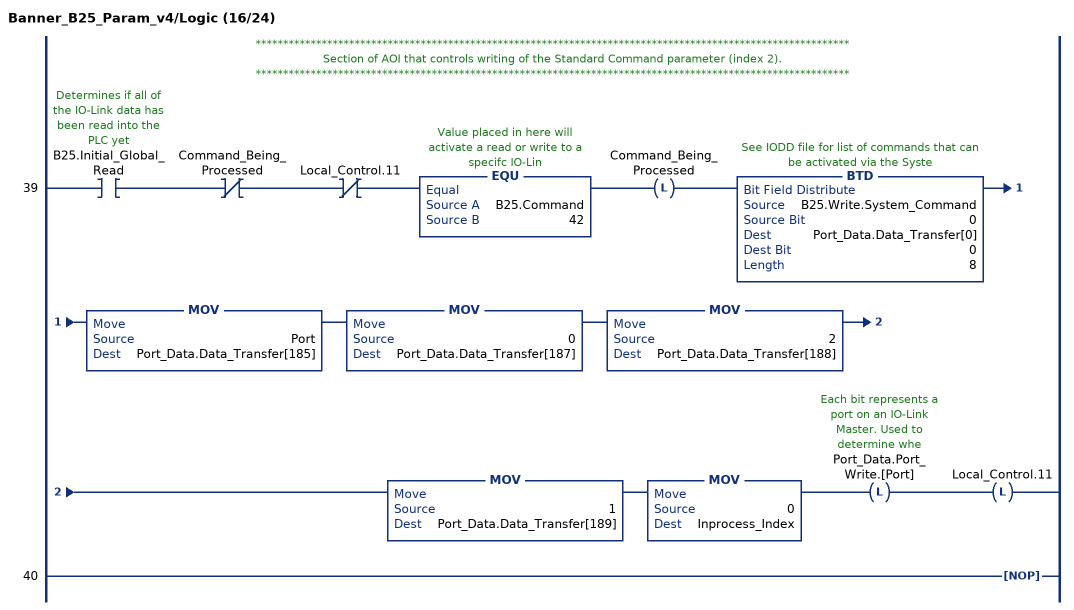
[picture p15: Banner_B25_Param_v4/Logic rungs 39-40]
   // ************************************************************************************************************
   // Section of AOI that controls writing of the Standard Command parameter (index 2).
   // ************************************************************************************************************
   39: XIC(B25.Initial_Global_Read)XIO(Command_Being_Processed)XIO(Local_Control.11)EQU(B25.Command,42)OTL(Command_Being_Processed)BTD(B25.Write.System_Command,0,Port_Data.Data_Transfer[0],0,8)MOV(Port,Port_Data.Data_Transfer[185])MOV(0,Port_Data.Data_Transfer[187])MOV(2,Port_Data.Data_Transfer[188])MOV(1,Port_Data.Data_Transfer[189])MOV(0,Inprocess_Index)OTL(Port_Data.Port_Write.[Port])OTL(Local_Control.11);
   40: NOP();
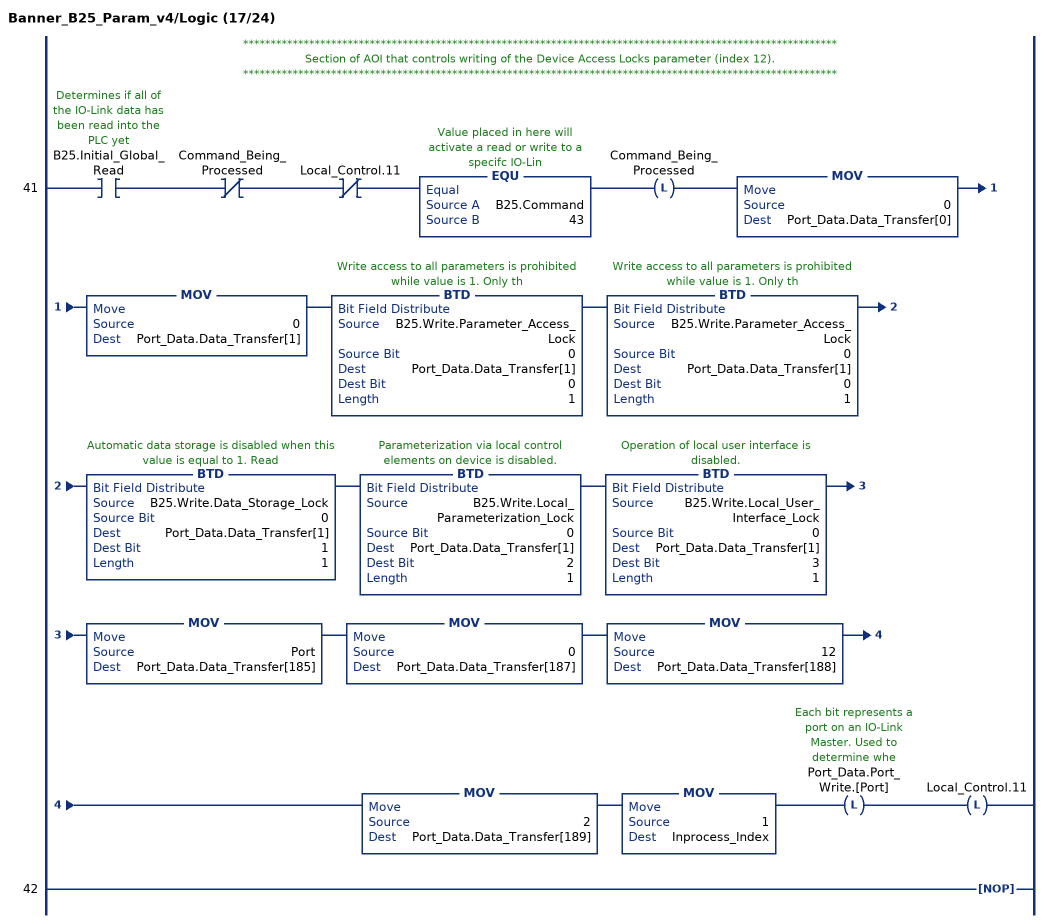
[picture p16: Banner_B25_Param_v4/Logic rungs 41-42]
   // ************************************************************************************************************
   // Section of AOI that controls writing of the Device Access Locks parameter (index 12).
   // ************************************************************************************************************
   41: XIC(B25.Initial_Global_Read)XIO(Command_Being_Processed)XIO(Local_Control.11)EQU(B25.Command,43)OTL(Command_Being_Processed)MOV(0,Port_Data.Data_Transfer[0])MOV(0,Port_Data.Data_Transfer[1])BTD(B25.Write.Parameter_Access_Lock,0,Port_Data.Data_Transfer[1],0,1)BTD(B25.Write.Parameter_Access_Lock,0,Port_Data.Data_Transfer[1],0,1)BTD(B25.Write.Data_Storage_Lock,0,Port_Data.Data_Transfer[1],1,1)BTD(B25.Write.Local_Parameterization_Lock,0,Port_Data.Data_Transfer[1],2,1)BTD(B25.Write.Local_User_Interface_Lock,0,Port_Data.Data_Transfer[1],3,1)MOV(Port,Port_Data.Data_Transfer[185])MOV(0,Port_Data.Data_Transfer[187])MOV(12,Port_Data.Data_Transfer[188])MOV(2,Port_Data.Data_Transfer[189])MOV(1,Inprocess_Index)OTL(Port_Data.Port_Write.[Port])OTL(Local_Control.11);
   42: NOP();
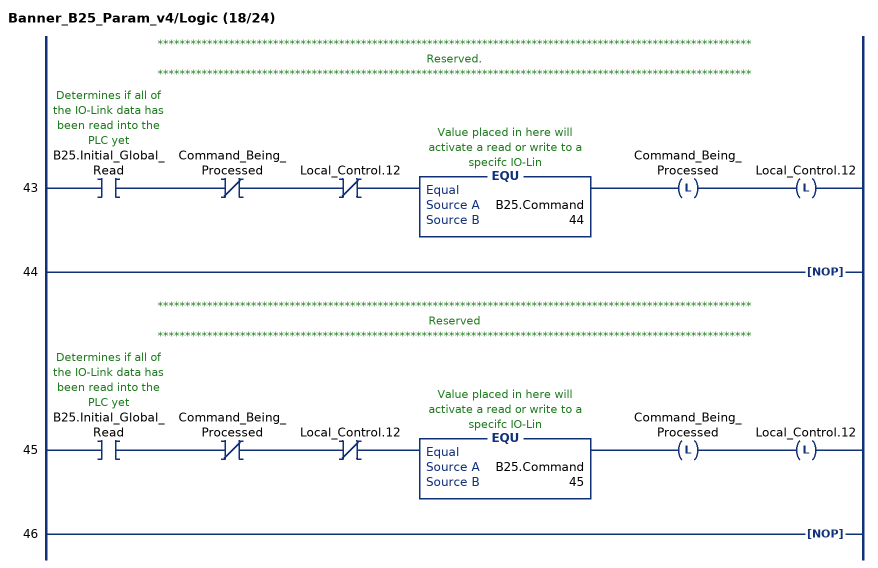
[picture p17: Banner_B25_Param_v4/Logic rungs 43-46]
   // ************************************************************************************************************
   // Reserved.
   // ************************************************************************************************************
   43: XIC(B25.Initial_Global_Read)XIO(Command_Being_Processed)XIO(Local_Control.12)EQU(B25.Command,44)OTL(Command_Being_Processed)OTL(Local_Control.12);
   44: NOP();
   // ************************************************************************************************************
   // Reserved
   // ************************************************************************************************************
   45: XIC(B25.Initial_Global_Read)XIO(Command_Being_Processed)XIO(Local_Control.12)EQU(B25.Command,45)OTL(Command_Being_Processed)OTL(Local_Control.12);
   46: NOP();
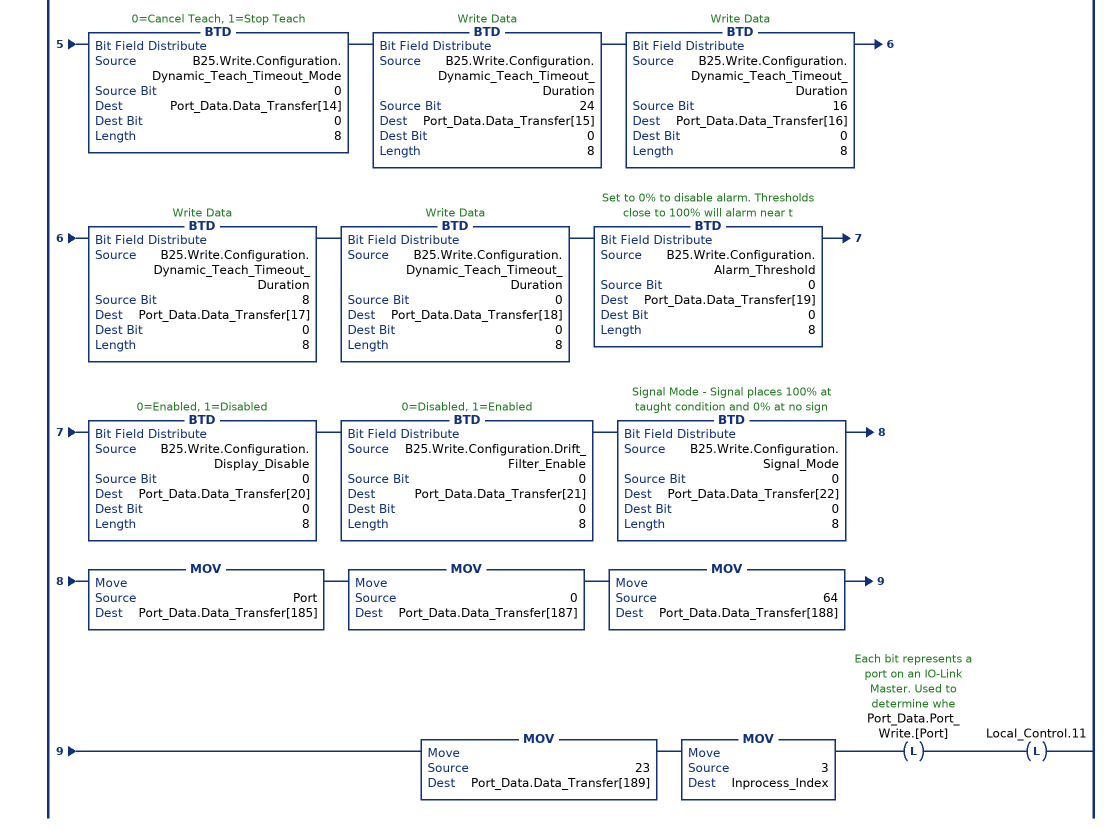
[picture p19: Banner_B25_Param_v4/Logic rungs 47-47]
   // ************************************************************************************************************
   // Section of AOI that controls writing of the Configuration parameter (index 64).
   // ************************************************************************************************************
   47: XIC(B25.Initial_Global_Read)XIO(Command_Being_Processed)XIO(Local_Control.11)EQU(B25.Command,46)OTL(Command_Being_Processed)BTD(B25.Write.Configuration.Sensor_Lockout,0,Port_Data.Data_Transfer[0],0,8)BTD(B25.Write.Configuration.Sensitivity,0,Port_Data.Data_Transfer[1],0,8)BTD(B25.Write.Configuration.Pin2_Function,0,Port_Data.Data_Transfer[2],0,8)BTD(B25.Write.Configuration.Pin2_Pin4_Polarity,0,Port_Data.Data_Transfer[3],0,8)BTD(B25.Write.Configuration.Output_Logic,0,Port_Data.Data_Transfer[4],0,8)BTD(B25.Write.Configuration.Output_Delay_Mode,0,Port_Data.Data_Transfer[5],0,8)BTD(B25.Write.Configuration.Output_On_Delay,24,Port_Data.Data_Transfer[6],0,8)BTD(B25.Write.Configuration.Output_On_Delay,16,Port_Data.Data_Transfer[7],0,8)BTD(B25.Write.Configuration.Output_On_Delay,8,Port_Data.Data_Transfer[8],0,8)BTD(B25.Write.Configuration.Output_On_Delay,0,Port_Data.Data_Transfer[9],0,8)BTD(B25.Write.Configuration.Output_Off_Delay,24,Port_Data.Data_Transfer[10],0,8)BTD(B25.Write.Configuration.Output_Off_Delay,16,Port_Data.Data_Transfer[11],0,8)BTD(B25.Write.Configuration.Output_Off_Delay,8,Port_Data.Data_Transfer[12],0,8)BTD(B25.Write.Configuration.Output_Off_Delay,0,Port_Data.Data_Transfer[13],0,8)BTD(B25.Write.Configuration.Dynamic_Teach_Timeout_Mode,0,Port_Data.Data_Transfer[14],0,8)BTD(B25.Write.Configuration.Dynamic_Teach_Timeout_Duration,24,Port_Data.Data_Transfer[15],0,8)BTD(B25.Write.Configuration.Dynamic_Teach_Timeout_Duration,16,Port_Data.Data_Transfer[16],0,8)BTD(B25.Write.Configuration.Dynamic_Teach_Timeout_Duration,8,Port_Data.Data_Transfer[17],0,8)BTD(B25.Write.Configuration.Dynamic_Teach_Timeout_Duration,0,Port_Data.Data_Transfer[18],0,8)BTD(B25.Write.Configuration.Alarm_Threshold,0,Port_Data.Data_Transfer[19],0,8)BTD(B25.Write.Configuration.Display_Disable,0,Port_Data.Data_Transfer[20],0,8)BTD(B25.Write.Configuration.Drift_Filter_Enable,0,Port_Data.Data_Transfer[21],0,8)BTD(B25.Write.Configuration.Signal_Mode,0,Port_Data.Data_Transfer[22],0,8)MOV(Port,Port_Data.Data_Transfer[185])MOV(0,Port_Data.Data_Transfer[187])MOV(64,Port_Data.Data_Transfer[188])MOV(23,Port_Data.Data_Transfer[189])MOV(3,Inprocess_Index)OTL(Port_Data.Port_Write.[Port])OTL(Local_Control.11);
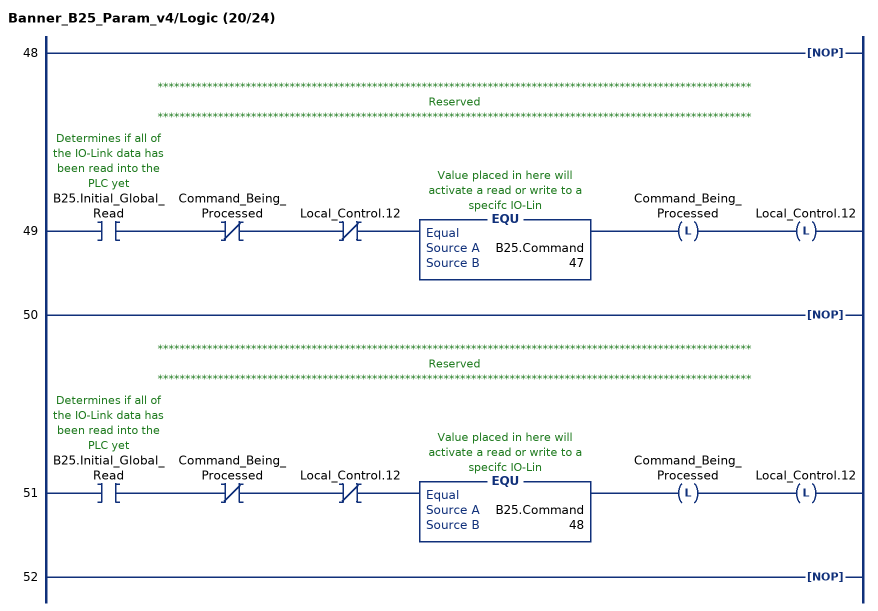
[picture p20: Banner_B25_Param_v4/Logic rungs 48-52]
   48: NOP();
   // ************************************************************************************************************
   // Reserved
   // ************************************************************************************************************
   49: XIC(B25.Initial_Global_Read)XIO(Command_Being_Processed)XIO(Local_Control.12)EQU(B25.Command,47)OTL(Command_Being_Processed)OTL(Local_Control.12);
   50: NOP();
   // ************************************************************************************************************
   // Reserved
   // ************************************************************************************************************
   51: XIC(B25.Initial_Global_Read)XIO(Command_Being_Processed)XIO(Local_Control.12)EQU(B25.Command,48)OTL(Command_Being_Processed)OTL(Local_Control.12);
   52: NOP();
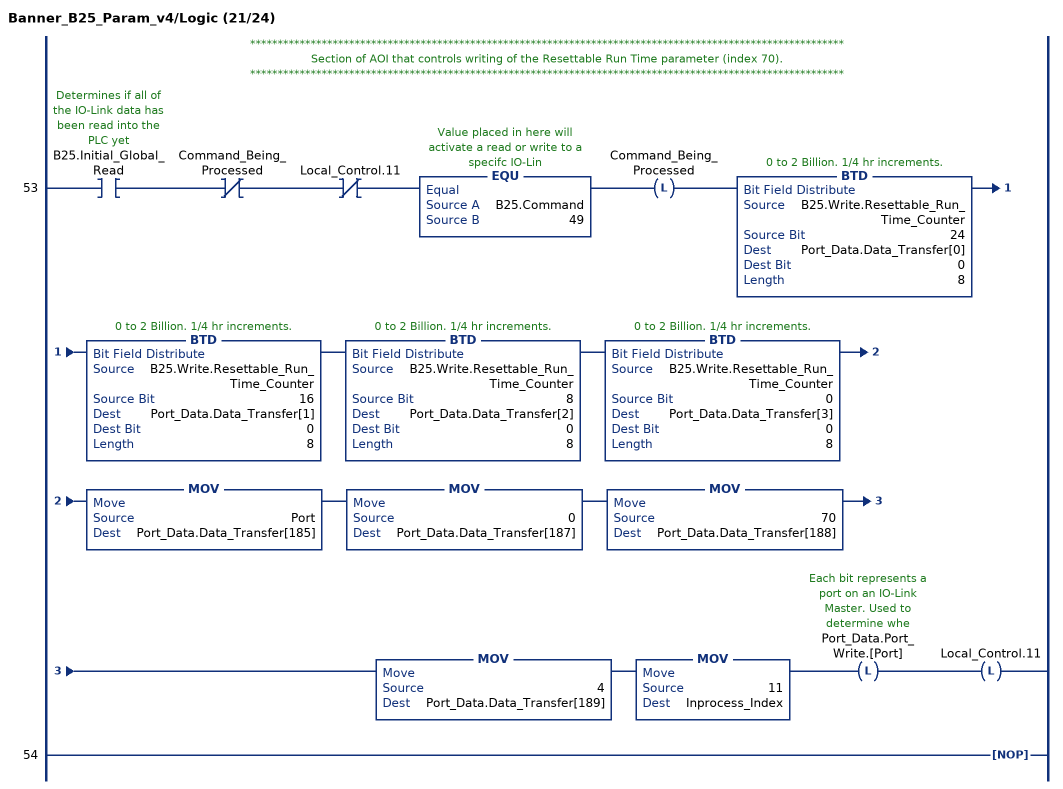
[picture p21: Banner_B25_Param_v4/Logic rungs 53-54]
   // ************************************************************************************************************
   // Section of AOI that controls writing of the Resettable Run Time parameter (index 70).
   // ************************************************************************************************************
   53: XIC(B25.Initial_Global_Read)XIO(Command_Being_Processed)XIO(Local_Control.11)EQU(B25.Command,49)OTL(Command_Being_Processed)BTD(B25.Write.Resettable_Run_Time_Counter,24,Port_Data.Data_Transfer[0],0,8)BTD(B25.Write.Resettable_Run_Time_Counter,16,Port_Data.Data_Transfer[1],0,8)BTD(B25.Write.Resettable_Run_Time_Counter,8,Port_Data.Data_Transfer[2],0,8)BTD(B25.Write.Resettable_Run_Time_Counter,0,Port_Data.Data_Transfer[3],0,8)MOV(Port,Port_Data.Data_Transfer[185])MOV(0,Port_Data.Data_Transfer[187])MOV(70,Port_Data.Data_Transfer[188])MOV(4,Port_Data.Data_Transfer[189])MOV(11,Inprocess_Index)OTL(Port_Data.Port_Write.[Port])OTL(Local_Control.11);
   54: NOP();
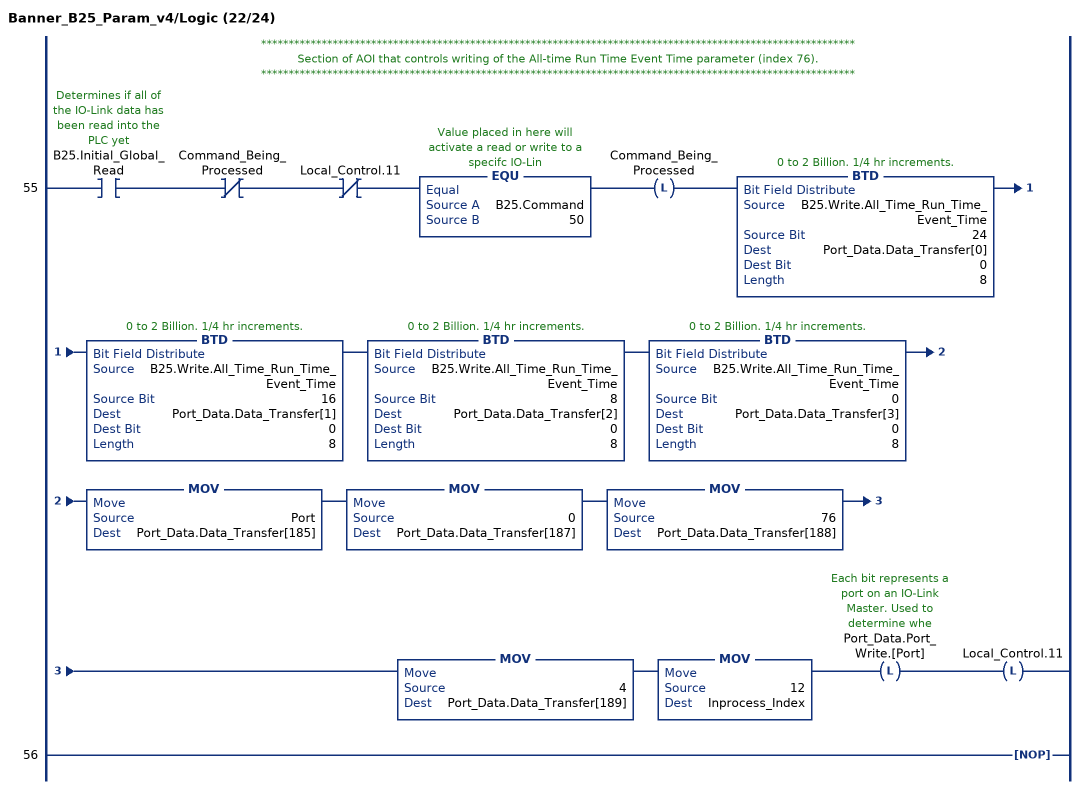
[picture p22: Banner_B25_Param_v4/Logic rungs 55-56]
   // ************************************************************************************************************
   // Section of AOI that controls writing of the All-time Run Time Event Time parameter (index 76).
   // ************************************************************************************************************
   55: XIC(B25.Initial_Global_Read)XIO(Command_Being_Processed)XIO(Local_Control.11)EQU(B25.Command,50)OTL(Command_Being_Processed)BTD(B25.Write.All_Time_Run_Time_Event_Time,24,Port_Data.Data_Transfer[0],0,8)BTD(B25.Write.All_Time_Run_Time_Event_Time,16,Port_Data.Data_Transfer[1],0,8)BTD(B25.Write.All_Time_Run_Time_Event_Time,8,Port_Data.Data_Transfer[2],0,8)BTD(B25.Write.All_Time_Run_Time_Event_Time,0,Port_Data.Data_Transfer[3],0,8)MOV(Port,Port_Data.Data_Transfer[185])MOV(0,Port_Data.Data_Transfer[187])MOV(76,Port_Data.Data_Transfer[188])MOV(4,Port_Data.Data_Transfer[189])MOV(12,Inprocess_Index)OTL(Port_Data.Port_Write.[Port])OTL(Local_Control.11);
   56: NOP();
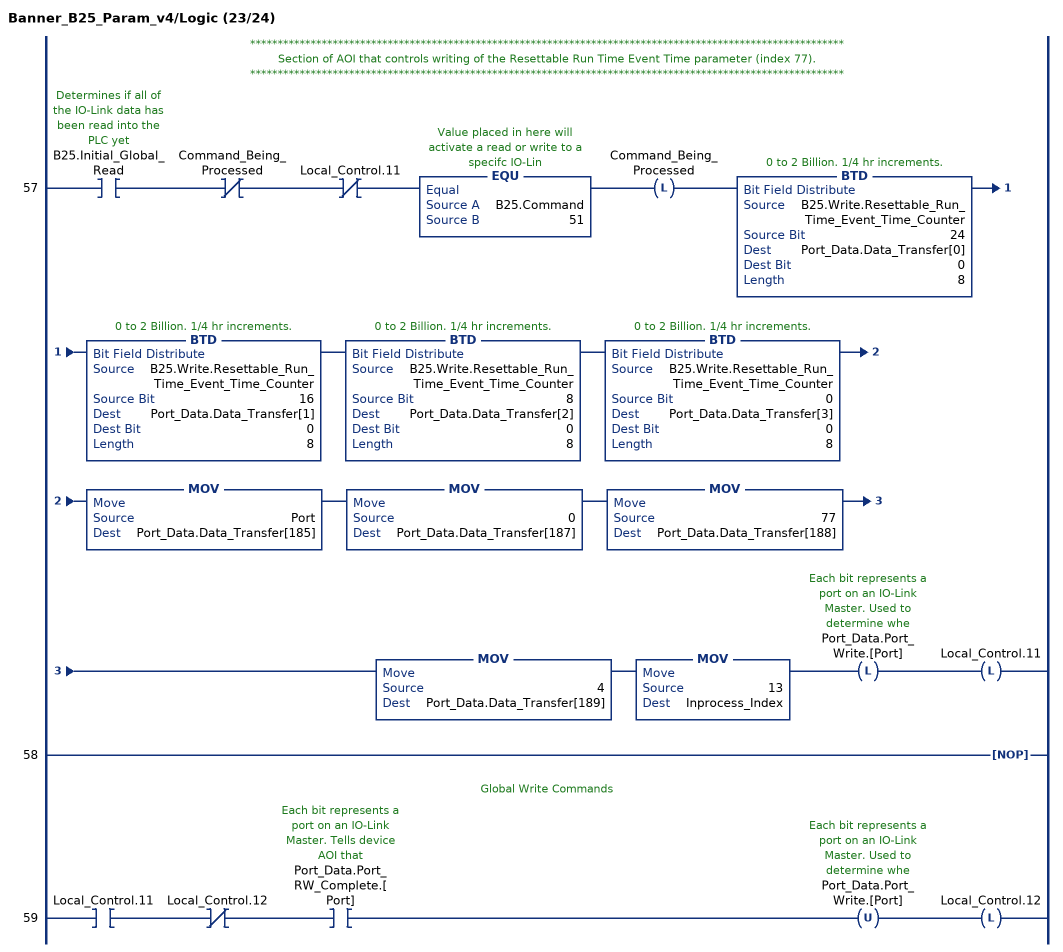
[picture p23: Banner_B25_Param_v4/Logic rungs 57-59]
   // ************************************************************************************************************
   // Section of AOI that controls writing of the Resettable Run Time Event Time parameter (index 77).
   // ************************************************************************************************************
   57: XIC(B25.Initial_Global_Read)XIO(Command_Being_Processed)XIO(Local_Control.11)EQU(B25.Command,51)OTL(Command_Being_Processed)BTD(B25.Write.Resettable_Run_Time_Event_Time_Counter,24,Port_Data.Data_Transfer[0],0,8)BTD(B25.Write.Resettable_Run_Time_Event_Time_Counter,16,Port_Data.Data_Transfer[1],0,8)BTD(B25.Write.Resettable_Run_Time_Event_Time_Counter,8,Port_Data.Data_Transfer[2],0,8)BTD(B25.Write.Resettable_Run_Time_Event_Time_Counter,0,Port_Data.Data_Transfer[3],0,8)MOV(Port,Port_Data.Data_Transfer[185])MOV(0,Port_Data.Data_Transfer[187])MOV(77,Port_Data.Data_Transfer[188])MOV(4,Port_Data.Data_Transfer[189])MOV(13,Inprocess_Index)OTL(Port_Data.Port_Write.[Port])OTL(Local_Control.11);
   58: NOP();
   // Global Write Commands
   59: XIC(Local_Control.11)XIO(Local_Control.12)XIC(Port_Data.Port_RW_Complete.[Port])OTU(Port_Data.Port_Write.[Port])OTL(Local_Control.12);
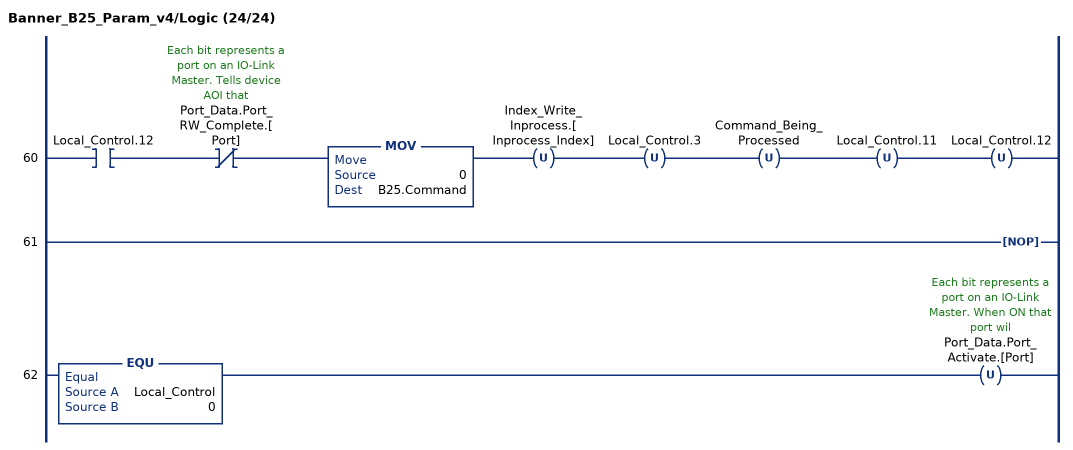
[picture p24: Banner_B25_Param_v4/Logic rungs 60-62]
   60: XIC(Local_Control.12)XIO(Port_Data.Port_RW_Complete.[Port])MOV(0,B25.Command)OTU(Index_Write_Inprocess.[Inprocess_Index])OTU(Local_Control.3)OTU(Command_Being_Processed)OTU(Local_Control.11)OTU(Local_Control.12);
   61: NOP();
   62: EQU(Local_Control,0)OTU(Port_Data.Port_Activate.[Port]);
END_ROUTINE
END_ADD_ON_INSTRUCTION
